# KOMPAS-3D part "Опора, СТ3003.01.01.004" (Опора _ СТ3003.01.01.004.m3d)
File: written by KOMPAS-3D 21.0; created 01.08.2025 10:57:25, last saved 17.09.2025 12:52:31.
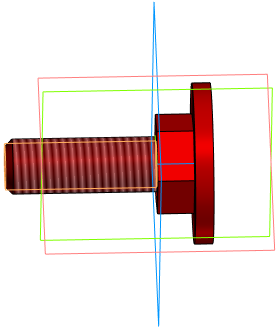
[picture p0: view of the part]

Document properties: Полное имя файла: C:\Users\1\Yandex.Disk\Документы\Новая папка\Стапель №2\Стапель _ СТ3003.00.00.000\Опора _ СТ3003.01.00.000\3D\Кронштейн _ СТ3003.01.01.000\Опора _ СТ3003.01.01.004.m3d; Автор: 1

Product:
- Part/product: Опора  | designation СТ3003.01.01.004
    Материал: Круг$d35 ГОСТ 2590-2006;Ст3сп ГОСТ 535-2005$ (density 7850 kg/m3)
    Масса: 0.078797
    Форматы листов документа: A4

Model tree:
1. Эскиз:1
2. Элемент выдавливания:1
     Расстояние 1 = 12
3. Эскиз:2
4. Элемент выдавливания:2
     Расстояние 1 = 33
5. Условное изображение резьбы:1  (with: Элемент выдавливания:2)  (labels: M12; cil0_24705-2004 coarse)
     Длина резьбы = 33; Шаг резьбы = 1.75; Номинальный диаметр резьбы = 12
6. Подгонка:1  (with: Элемент выдавливания:2)
7. Фаска:1  (with: Элемент выдавливания:2)
     Угол = 45; Длина 1 = 1.6; Длина 2 = 1.6
8. Эскиз:3  (with: Элемент выдавливания:1, Элемент выдавливания:2)
9. Элемент выдавливания:3  (labels: Круг$d35 ГОСТ 2590-2006;Ст3сп ГОСТ 535-2005$)
     Расстояние 2 = 8

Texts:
  СТ3003.01.01.004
